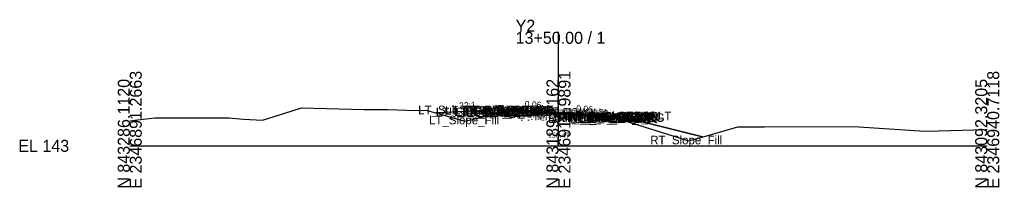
# Model space of a CAD drawing. Extents: x -26 to 2346977, y -10 to 843253.
# Drawn here: x -25.7 to 202.8, y 2990.3 to 3029.4 of the extents above; entities that cross this region are included whole.
import ezdxf

# ---------------------------------------------------------------- set-up
doc = ezdxf.new("R2010")
doc.units = 0
for name, color, linetype in [('Default', 7, 'Continuous'), ('Exist CMT Pavement', 7, 'Continuous'), ('Exist Cross Section Cell', 7, 'Continuous'), ('Exist XS Center Line Elevation Label', 7, 'Continuous'), ('Exist XS Ground Line', 7, 'Continuous'), ('Prop CMT Pvmt Course 1', 7, 'Continuous'), ('Prop CMT Pvmt Course 1 Wedge', 7, 'Continuous'), ('Prop CMT Pvmt Course 2', 7, 'Continuous'), ('Prop CMT Pvmt Course 2 Wedge', 7, 'Continuous'), ('Prop CMT Pvmt Course 3', 7, 'Continuous'), ('Prop CMT Pvmt Course 3 Wedge', 7, 'Continuous'), ('Prop CMT Pvmt Surface', 7, 'Continuous'), ('Prop CMT Pvmt Surface Shoulder', 7, 'Continuous'), ('Prop CMT Pvmt Wedge Surface 1', 7, 'Continuous'), ('Prop CMT Pvmt Wedge Surface 2', 7, 'Continuous'), ('Prop CMT Pvmt Wedge Surface 3', 7, 'Continuous'), ('Prop CMT Shld Paved Course 1', 7, 'Continuous'), ('Prop CMT Shld Paved Course 2', 7, 'Continuous'), ('Prop CMT Shld Paved Course 3', 7, 'Continuous'), ('Prop CMT Slope Grass', 7, 'Continuous'), ('Prop CMT Subgrade Earthwork', 7, 'Continuous'), ('Prop XS Earthwork Shape', 7, 'Continuous'), ('Prop XS SE Text', 7, 'Continuous'), ('Scratch_Level_2', 7, 'Continuous')]:
    doc.layers.add(name, color=color, linetype=linetype)

msp = doc.modelspace()

# ---------------------------------------------------------------- linework, layer by layer
at = {"layer": 'Exist CMT Pavement'}
for p, q in [((88.28, 3007.99), (88.44, 3007.98)), ((88.44, 3007.98), (90.76, 3007.9)), ((90.76, 3007.9), (92.15, 3007.84)), ((92.15, 3007.84), (93.37, 3007.78)), ((93.37, 3007.78), (95.34, 3007.69)), ((95.34, 3007.69), (95.92, 3007.67)), ((95.92, 3007.67), (97.6, 3007.58)), ((97.6, 3007.58), (98.31, 3007.54)), ((98.31, 3007.54), (98.5, 3007.53)), ((98.5, 3007.53), (99.16, 3007.5)), ((99.16, 3007.5), (100, 3007.47)), ((100, 3007.47), (100.43, 3007.45)), ((100.43, 3007.45), (100.56, 3007.43)), ((100.56, 3007.43), (101.06, 3007.39)), ((101.06, 3007.39), (102.26, 3007.31)), ((102.26, 3007.31), (103.62, 3007.22)), ((103.62, 3007.22), (104.44, 3007.17)), ((104.44, 3007.17), (106.2, 3007.05)), ((106.2, 3007.05), (107.65, 3006.94)), ((107.65, 3006.94), (108.79, 3006.85)), ((108.79, 3006.85), (110.71, 3006.7)), ((110.71, 3006.7), (111.52, 3006.63)), ((111.52, 3006.63), (111.83, 3006.62)), ((111.83, 3006.62), (112.28, 3006.58))]:
    msp.add_line(p, q, dxfattribs=at)
at = {"layer": 'Exist Cross Section Cell'}
for p, q in [((100, 3000), (100, 3026.6)), ((0, 3000), (100, 3000)), ((100, 3000), (200, 3000))]:
    msp.add_line(p, q, dxfattribs=at)
at = {"layer": 'Exist XS Ground Line'}
msp.add_lwpolyline([(0, 3005.86), (1.8, 3006.08), (5.88, 3006.52), (15.27, 3006.5), (23.13, 3006.52), (26.56, 3006.24), (30.96, 3005.95), (35.9, 3007.53), (40.07, 3008.87), (54.58, 3008.51), (60.14, 3008.46), (64.65, 3008.3), (69.34, 3008.24), (78.12, 3005.74), (87.86, 3008.01), (88.44, 3007.98), (90.76, 3007.9), (92.15, 3007.84), (93.37, 3007.78), (95.34, 3007.69), (95.92, 3007.67), (97.6, 3007.58), (98.5, 3007.53), (99.16, 3007.5), (100, 3007.47), (100.43, 3007.45), (101.06, 3007.39), (102.26, 3007.31), (103.62, 3007.22), (104.44, 3007.17), (106.2, 3007.05), (107.65, 3006.94), (108.79, 3006.85), (110.71, 3006.7), (111.52, 3006.63), (111.83, 3006.62), (112.54, 3006.57), (112.86, 3006.49), (116.27, 3005.63), (126.64, 3002.33), (130.29, 3001.18), (133.5, 3002.06), (141.85, 3004.44), (142.5, 3004.44), (148.08, 3004.45), (168.14, 3004.5), (170.03, 3004.43), (181.96, 3003.64), (182.91, 3003.59), (185.67, 3003.45), (191.44, 3003.6), (199.57, 3003.79), (200, 3003.79)], dxfattribs=at)
at = {"layer": 'Prop CMT Pvmt Course 1'}
for p, q in [((100, 3007.8), (88.28, 3008.5)), ((88.28, 3008.5), (88.28, 3008.25)), ((88.28, 3008.25), (88.28, 3008.38)), ((88.28, 3008.38), (100, 3007.68)), ((88.28, 3008.25), (88.28, 3008.25)), ((100, 3007.55), (100, 3007.8)), ((100, 3007.8), (112.28, 3007.06)), ((100, 3007.55), (100, 3007.8)), ((100, 3007.68), (100, 3007.55)), ((112.28, 3006.94), (100, 3007.68)), ((100, 3007.68), (100, 3007.55)), ((100, 3007.55), (100, 3007.55)), ((100, 3007.55), (100, 3007.55)), ((112.28, 3007.06), (112.28, 3006.81)), ((112.28, 3006.81), (112.28, 3006.94)), ((112.28, 3006.81), (112.28, 3006.81))]:
    msp.add_line(p, q, dxfattribs=at)
at = {"layer": 'Prop CMT Pvmt Course 1 Wedge'}
for p, q in [((88.28, 3008.38), (88.44, 3008.37)), ((88.28, 3008.25), (88.28, 3008.38)), ((88.44, 3008.24), (88.28, 3008.25)), ((88.44, 3008.37), (90.76, 3008.23)), ((90.76, 3008.1), (88.44, 3008.24)), ((90.76, 3008.23), (92.15, 3008.15)), ((92.15, 3008.02), (90.76, 3008.1)), ((92.15, 3008.15), (93.37, 3008.07)), ((93.37, 3007.95), (92.15, 3008.02)), ((93.37, 3008.07), (95.34, 3007.95)), ((95.34, 3007.83), (93.37, 3007.95)), ((95.34, 3007.95), (95.92, 3007.92)), ((95.92, 3007.8), (95.34, 3007.83)), ((95.92, 3007.92), (97.6, 3007.82)), ((97.6, 3007.69), (95.92, 3007.8)), ((97.6, 3007.82), (98.31, 3007.78)), ((98.31, 3007.65), (97.6, 3007.69)), ((98.31, 3007.78), (98.5, 3007.77)), ((98.5, 3007.64), (98.31, 3007.65)), ((98.5, 3007.77), (99.16, 3007.73)), ((99.16, 3007.6), (98.5, 3007.64)), ((99.16, 3007.73), (100, 3007.68)), ((100, 3007.55), (99.16, 3007.6)), ((100, 3007.68), (100, 3007.55)), ((100, 3007.68), (100.43, 3007.65)), ((100, 3007.55), (100, 3007.68)), ((100.43, 3007.52), (100, 3007.55)), ((100.43, 3007.65), (100.56, 3007.64)), ((100.56, 3007.52), (100.43, 3007.52)), ((100.56, 3007.64), (101.06, 3007.61)), ((101.06, 3007.49), (100.56, 3007.52)), ((101.06, 3007.61), (102.26, 3007.54)), ((102.26, 3007.54), (103.62, 3007.46)), ((102.26, 3007.41), (101.06, 3007.49)), ((103.62, 3007.33), (102.26, 3007.41)), ((103.62, 3007.46), (104.44, 3007.41)), ((104.44, 3007.28), (103.62, 3007.33)), ((104.44, 3007.41), (106.2, 3007.3)), ((106.2, 3007.18), (104.44, 3007.28)), ((106.2, 3007.3), (107.65, 3007.22)), ((107.65, 3007.09), (106.2, 3007.18)), ((107.65, 3007.22), (108.79, 3007.15)), ((108.79, 3007.02), (107.65, 3007.09)), ((108.79, 3007.15), (110.71, 3007.03)), ((110.71, 3006.91), (108.79, 3007.02)), ((110.71, 3007.03), (111.52, 3006.98)), ((111.52, 3006.86), (110.71, 3006.91)), ((111.52, 3006.98), (111.83, 3006.97)), ((111.83, 3006.84), (111.52, 3006.86)), ((111.83, 3006.97), (112.28, 3006.94)), ((112.28, 3006.81), (111.83, 3006.84)), ((112.28, 3006.94), (112.28, 3006.81))]:
    msp.add_line(p, q, dxfattribs=at)
at = {"layer": 'Prop CMT Pvmt Course 2'}
for p, q in [((88.28, 3008.25), (88.28, 3008.25)), ((88.28, 3008.25), (88.28, 3008.25)), ((88.28, 3008.25), (88.28, 3008.25)), ((88.28, 3008.25), (88.28, 3008.25)), ((112.28, 3006.81), (112.28, 3006.81)), ((112.28, 3006.81), (112.28, 3006.81)), ((112.28, 3006.81), (112.28, 3006.81)), ((112.28, 3006.81), (112.28, 3006.81))]:
    msp.add_line(p, q, dxfattribs=at)
at = {"layer": 'Prop CMT Pvmt Course 2 Wedge'}
for p, q in [((88.28, 3008.25), (88.44, 3008.24)), ((88.28, 3008), (88.28, 3008.25)), ((88.44, 3007.99), (88.28, 3008)), ((88.44, 3008.24), (90.76, 3008.1)), ((88.91, 3007.97), (88.44, 3007.99)), ((90.76, 3007.9), (88.91, 3007.97)), ((90.76, 3008.1), (92.15, 3008.02)), ((92.15, 3007.84), (90.76, 3007.9)), ((92.15, 3008.02), (93.37, 3007.95)), ((93.37, 3007.78), (92.15, 3007.84)), ((93.37, 3007.95), (95.34, 3007.83)), ((95.34, 3007.69), (93.37, 3007.78)), ((95.34, 3007.83), (95.92, 3007.8)), ((95.92, 3007.67), (95.34, 3007.69)), ((95.92, 3007.8), (97.6, 3007.69)), ((97.6, 3007.58), (95.92, 3007.67)), ((97.6, 3007.69), (98.31, 3007.65)), ((98.31, 3007.54), (97.6, 3007.58)), ((98.31, 3007.65), (98.5, 3007.64)), ((98.5, 3007.53), (98.31, 3007.54)), ((98.5, 3007.64), (99.16, 3007.6)), ((99.16, 3007.5), (98.5, 3007.53)), ((99.16, 3007.6), (100, 3007.55)), ((100, 3007.47), (99.16, 3007.5)), ((100, 3007.55), (100, 3007.47)), ((100, 3007.55), (100.43, 3007.52)), ((100, 3007.47), (100, 3007.55)), ((100.43, 3007.52), (100.56, 3007.52)), ((100.56, 3007.52), (101.06, 3007.49)), ((100.43, 3007.45), (100, 3007.47)), ((100.56, 3007.43), (100.43, 3007.45)), ((101.06, 3007.39), (100.56, 3007.43)), ((101.06, 3007.49), (102.26, 3007.41)), ((102.26, 3007.31), (101.06, 3007.39)), ((102.26, 3007.41), (103.62, 3007.33)), ((103.62, 3007.22), (102.26, 3007.31)), ((103.62, 3007.33), (104.44, 3007.28)), ((104.44, 3007.17), (103.62, 3007.22)), ((104.44, 3007.28), (106.2, 3007.18)), ((106.2, 3007.05), (104.44, 3007.17)), ((106.2, 3007.18), (107.65, 3007.09)), ((107.65, 3006.94), (106.2, 3007.05)), ((107.65, 3007.09), (108.79, 3007.02)), ((108.79, 3006.85), (107.65, 3006.94)), ((108.79, 3007.02), (110.71, 3006.91)), ((110.71, 3006.7), (108.79, 3006.85)), ((110.71, 3006.91), (111.52, 3006.86)), ((111.52, 3006.63), (110.71, 3006.7)), ((111.52, 3006.86), (111.83, 3006.84)), ((111.83, 3006.62), (111.52, 3006.63)), ((111.83, 3006.84), (112.28, 3006.81)), ((112.28, 3006.58), (111.83, 3006.62)), ((112.28, 3006.81), (112.28, 3006.58))]:
    msp.add_line(p, q, dxfattribs=at)
at = {"layer": 'Prop CMT Pvmt Course 3'}
for p, q in [((88.28, 3008.25), (88.28, 3008.25)), ((88.28, 3008.25), (88.28, 3007.99)), ((88.28, 3007.99), (88.28, 3008.25)), ((112.28, 3006.81), (112.28, 3006.81)), ((112.28, 3006.81), (112.28, 3006.48)), ((112.28, 3006.48), (112.28, 3006.81)), ((112.28, 3006.48), (112.28, 3006.48))]:
    msp.add_line(p, q, dxfattribs=at)
at = {"layer": 'Prop CMT Pvmt Course 3 Wedge'}
for p, q in [((88.28, 3008.25), (88.44, 3008.24)), ((88.28, 3007.99), (88.28, 3008.25)), ((88.44, 3007.98), (88.28, 3007.99)), ((88.44, 3008.24), (90.76, 3008.1)), ((90.76, 3007.9), (88.44, 3007.98)), ((90.76, 3008.1), (92.15, 3008.02)), ((92.15, 3007.84), (90.76, 3007.9)), ((92.15, 3008.02), (93.37, 3007.95)), ((93.37, 3007.78), (92.15, 3007.84)), ((93.37, 3007.95), (95.34, 3007.83)), ((95.34, 3007.69), (93.37, 3007.78)), ((95.34, 3007.83), (95.92, 3007.8)), ((95.92, 3007.67), (95.34, 3007.69)), ((95.92, 3007.8), (97.6, 3007.69)), ((97.6, 3007.58), (95.92, 3007.67)), ((97.6, 3007.69), (98.31, 3007.65)), ((98.31, 3007.54), (97.6, 3007.58)), ((98.31, 3007.65), (98.5, 3007.64)), ((98.5, 3007.53), (98.31, 3007.54)), ((98.5, 3007.64), (99.16, 3007.6)), ((99.16, 3007.5), (98.5, 3007.53)), ((99.16, 3007.6), (100, 3007.55)), ((100, 3007.47), (99.16, 3007.5)), ((100, 3007.55), (100, 3007.47)), ((100, 3007.55), (100.43, 3007.52)), ((100, 3007.47), (100, 3007.55)), ((100.43, 3007.52), (100.56, 3007.52)), ((100.56, 3007.52), (101.06, 3007.49)), ((100.43, 3007.45), (100, 3007.47)), ((100.56, 3007.43), (100.43, 3007.45)), ((101.06, 3007.39), (100.56, 3007.43)), ((101.06, 3007.49), (102.26, 3007.41)), ((102.26, 3007.31), (101.06, 3007.39)), ((102.26, 3007.41), (103.62, 3007.33)), ((103.62, 3007.22), (102.26, 3007.31)), ((103.62, 3007.33), (104.44, 3007.28)), ((104.44, 3007.17), (103.62, 3007.22)), ((104.44, 3007.28), (106.2, 3007.18)), ((106.2, 3007.05), (104.44, 3007.17)), ((106.2, 3007.18), (107.65, 3007.09)), ((107.65, 3006.94), (106.2, 3007.05)), ((107.65, 3007.09), (108.79, 3007.02)), ((108.79, 3006.85), (107.65, 3006.94)), ((108.79, 3007.02), (110.71, 3006.91)), ((110.71, 3006.7), (108.79, 3006.85)), ((110.71, 3006.91), (111.52, 3006.86)), ((111.52, 3006.63), (110.71, 3006.7)), ((111.52, 3006.86), (111.83, 3006.84)), ((111.83, 3006.62), (111.52, 3006.63)), ((111.83, 3006.84), (112.28, 3006.81)), ((112.28, 3006.58), (111.83, 3006.62)), ((112.28, 3006.81), (112.28, 3006.58))]:
    msp.add_line(p, q, dxfattribs=at)
at = {"layer": 'Prop CMT Pvmt Surface'}
for q in [(88.28, 3008.5), (112.28, 3007.06)]:
    msp.add_line((100, 3007.8), q, dxfattribs=at)
at = {"layer": 'Prop CMT Pvmt Surface Shoulder'}
for p, q in [((88.28, 3008.5), (88.28, 3008.5)), ((112.28, 3007.06), (112.28, 3007.06))]:
    msp.add_line(p, q, dxfattribs=at)
at = {"layer": 'Prop CMT Pvmt Wedge Surface 1'}
for p, q in [((88.28, 3008.25), (88.28, 3008.5)), ((100, 3007.68), (88.28, 3008.38)), ((88.28, 3008.38), (88.28, 3008.25)), ((88.28, 3008.25), (88.28, 3008.25)), ((100, 3007.68), (112.28, 3006.94)), ((112.28, 3006.81), (112.28, 3007.06)), ((112.28, 3006.94), (112.28, 3006.81)), ((112.28, 3006.81), (112.28, 3006.81))]:
    msp.add_line(p, q, dxfattribs=at)
at = {"layer": 'Prop CMT Pvmt Wedge Surface 2'}
for p, q in [((88.28, 3008.25), (88.28, 3008.5)), ((100, 3007.55), (88.28, 3008.25)), ((100, 3007.55), (112.28, 3006.81)), ((112.28, 3006.81), (112.28, 3007.06))]:
    msp.add_line(p, q, dxfattribs=at)
at = {"layer": 'Prop CMT Pvmt Wedge Surface 3'}
for p, q in [((88.28, 3008.25), (88.28, 3008.5)), ((100, 3007.55), (88.28, 3008.25)), ((100, 3007.55), (112.28, 3006.81)), ((112.28, 3006.81), (112.28, 3007.06))]:
    msp.add_line(p, q, dxfattribs=at)
at = {"layer": 'Prop CMT Shld Paved Course 1'}
for p, q in [((88.28, 3008.5), (88.28, 3008.5)), ((88.28, 3008.25), (88.28, 3008.5)), ((112.28, 3007.06), (112.28, 3007.06)), ((112.28, 3007.06), (112.53, 3006.81)), ((112.28, 3006.81), (112.28, 3007.06)), ((112.53, 3006.81), (112.28, 3006.81))]:
    msp.add_line(p, q, dxfattribs=at)
at = {"layer": 'Prop CMT Shld Paved Course 2'}
for p, q in [((88.28, 3008.25), (88.28, 3008.25)), ((112.28, 3006.81), (112.53, 3006.81)), ((112.53, 3006.81), (112.28, 3006.81)), ((112.28, 3006.81), (112.28, 3006.81)), ((112.53, 3006.81), (112.53, 3006.81))]:
    msp.add_line(p, q, dxfattribs=at)
at = {"layer": 'Prop CMT Shld Paved Course 3'}
for p, q in [((88.28, 3007.99), (88.28, 3008.25)), ((112.28, 3006.81), (112.53, 3006.81)), ((112.28, 3006.48), (112.28, 3006.81)), ((113.37, 3006.46), (112.28, 3006.48)), ((112.53, 3006.81), (113.03, 3006.8)), ((113.03, 3006.8), (113.37, 3006.46))]:
    msp.add_line(p, q, dxfattribs=at)
at = {"layer": 'Prop CMT Slope Grass'}
for p, q in [((86.28, 3008.34), (71.37, 3007.67)), ((88.28, 3008.5), (86.28, 3008.34)), ((112.28, 3007.06), (114.28, 3006.9)), ((114.28, 3006.9), (133.58, 3002.08))]:
    msp.add_line(p, q, dxfattribs=at)
at = {"layer": 'Prop CMT Subgrade Earthwork'}
for p, q in [((112.28, 3006.48), (112.28, 3006.58)), ((112.28, 3006.48), (113.37, 3006.46)), ((112.28, 3006.48), (112.28, 3006.48)), ((113.37, 3006.46), (113.85, 3006.94))]:
    msp.add_line(p, q, dxfattribs=at)
at = {"layer": 'Prop XS Earthwork Shape'}
for points in [[(97.6, 3007.58), (98.31, 3007.54), (98.5, 3007.53)], [(100.56, 3007.43), (101.06, 3007.39), (100.43, 3007.45)], [(112.28, 3006.48), (112.28, 3006.58), (112.54, 3006.57), (112.86, 3006.49), (112.97, 3006.47)], [(116.27, 3005.63), (126.64, 3002.33), (130.29, 3001.18), (133.5, 3002.06), (133.58, 3002.08), (114.28, 3006.9), (113.85, 3006.94), (113.37, 3006.46), (112.97, 3006.47)]]:
    msp.add_lwpolyline(points, close=True, dxfattribs=at)

# ---------------------------------------------------------------- texts
at = {"layer": 'Default'}
msp.add_text('-', height=0.0001, dxfattribs=at).set_placement((0, 3000))
at = {"layer": 'Exist Cross Section Cell'}
for s, p in [('Y2', (90, 3026.6)), ('13+50.00 / 1', (90, 3023.8)), ('EL 143', (-26, 2998.6))]:
    msp.add_text(s, height=2.8, dxfattribs=at).set_placement(p)
for s, p in [('E 2346891.2663', (2.8, 2990)), ('E 2346915.9891', (102.8, 2990)), ('E 2346940.7118', (202.8, 2990)), ('N 843286.1120', (0, 2990)), ('N 843189.2162', (100, 2990)), ('N 843092.3205', (200, 2990))]:
    msp.add_text(s, height=2.8, rotation=90, dxfattribs=at).set_placement(p)
at = {"layer": 'Exist XS Center Line Elevation Label'}
msp.add_text('150.47', height=1.2, dxfattribs=at).set_placement((97.51, 3001.87))
at = {"layer": 'Prop XS SE Text'}
for s, rotation, p in [('22:1', 2.6026, (76.83, 3008.62)), ('0.06', 356.5664, (92.08, 3008.99)), ('0.06', 356.5664, (104.08, 3007.98)), ('4:1', 345.9638, (120.46, 3005.9))]:
    msp.add_text(s, height=1.5, rotation=rotation, dxfattribs=at).set_placement(p)
at = {"layer": 'Scratch_Level_2'}
for s, p in [('LT_Sub_Trench_Out_DLT', (67.27, 3007.38)), ('LT_Sub_Trench_Out', (71.39, 3006.9)), ('LT_PS3_Shelf_Out', (73.51, 3007.24)), ('LT_Sub Tie Out', (75.62, 3006.99)), ('LT_GS_OS_CTL', (75.65, 3007.34)), ('LT_PV_OEEOP_EG', (75.82, 3006.99)), ('LT_Sub_OEEOP', (77.49, 3006.92)), ('LT_PV2_OEEOP', (77.58, 3007.25)), ('LT_PV3_OEEOP', (77.58, 3007.25)), ('LT_PV1_OEEOP', (78.15, 3007.38)), ('LT_PS3_OEOP', (78.26, 3007.25)), ('LT_PS2_OEOP', (78.26, 3007.25)), ('LT_Sub_OEOT', (78.36, 3006.92)), ('LT_PV3_OEOT', (78.45, 3007.25)), ('LT_PV2_OEOT', (78.45, 3007.25)), ('LT_PV1_OEOT', (79.02, 3007.5)), ('LT_PS1_OEOP', (79.08, 3007.5)), ('RT_PV_IEEOP_EG', (88.14, 3006.47)), ('LT_PV_IEEOP_EG', (88.19, 3006.47)), ('RT_PV2_IEEOP', (89.91, 3006.55)), ('RT_PV3_IEEOP', (89.91, 3006.55)), ('LT_PV2_IEEOP', (89.95, 3006.55)), ('LT_PV3_IEEOP', (89.95, 3006.55)), ('RT_PV1_IEEOP', (90.47, 3006.68)), ('LT_PV1_IEEOP', (90.52, 3006.68)), ('PV2_PGL', (93.91, 3006.55)), ('RT_Sub_Trench_Out_DLT', (94.37, 3005.94)), ('PV1_PGL', (94.47, 3006.8)), ('RT_Sub_Trench_Out', (97.53, 3005.46)), ('RT_PS3_Shelf_Out', (98.97, 3005.8)), ('RT_Sub Tie Out', (99.57, 3005.58)), ('RT_PV_OEEOP_EG', (99.77, 3005.58)), ('RT_Sub_OEEOP', (101.44, 3005.48)), ('RT_PV2_OEEOP', (101.54, 3005.81)), ('RT_PV3_OEEOP', (101.54, 3005.81)), ('RT_PV1_OEEOP', (102.1, 3005.94)), ('RT_Sub_OEOT', (102.31, 3005.48)), ('RT_PV3_OEOT', (102.4, 3005.81)), ('RT_PV2_OEOT', (102.4, 3005.81)), ('RT_PS3_OEOP', (102.72, 3005.81)), ('RT_PS2_OEOP', (102.72, 3005.81)), ('RT_PV1_OEOT', (102.97, 3006.06)), ('RT_PS1_OEOP', (103.03, 3006.06)), ('RT_GS_OS_CTL', (103.6, 3005.9)), ('LT_Slope_Fill', (69.81, 3005.02)), ('RT_Slope_Fill', (121.4, 3000.35))]:
    msp.add_text(s, height=2, dxfattribs=at).set_placement(p)

doc.saveas('drawing.dxf')
